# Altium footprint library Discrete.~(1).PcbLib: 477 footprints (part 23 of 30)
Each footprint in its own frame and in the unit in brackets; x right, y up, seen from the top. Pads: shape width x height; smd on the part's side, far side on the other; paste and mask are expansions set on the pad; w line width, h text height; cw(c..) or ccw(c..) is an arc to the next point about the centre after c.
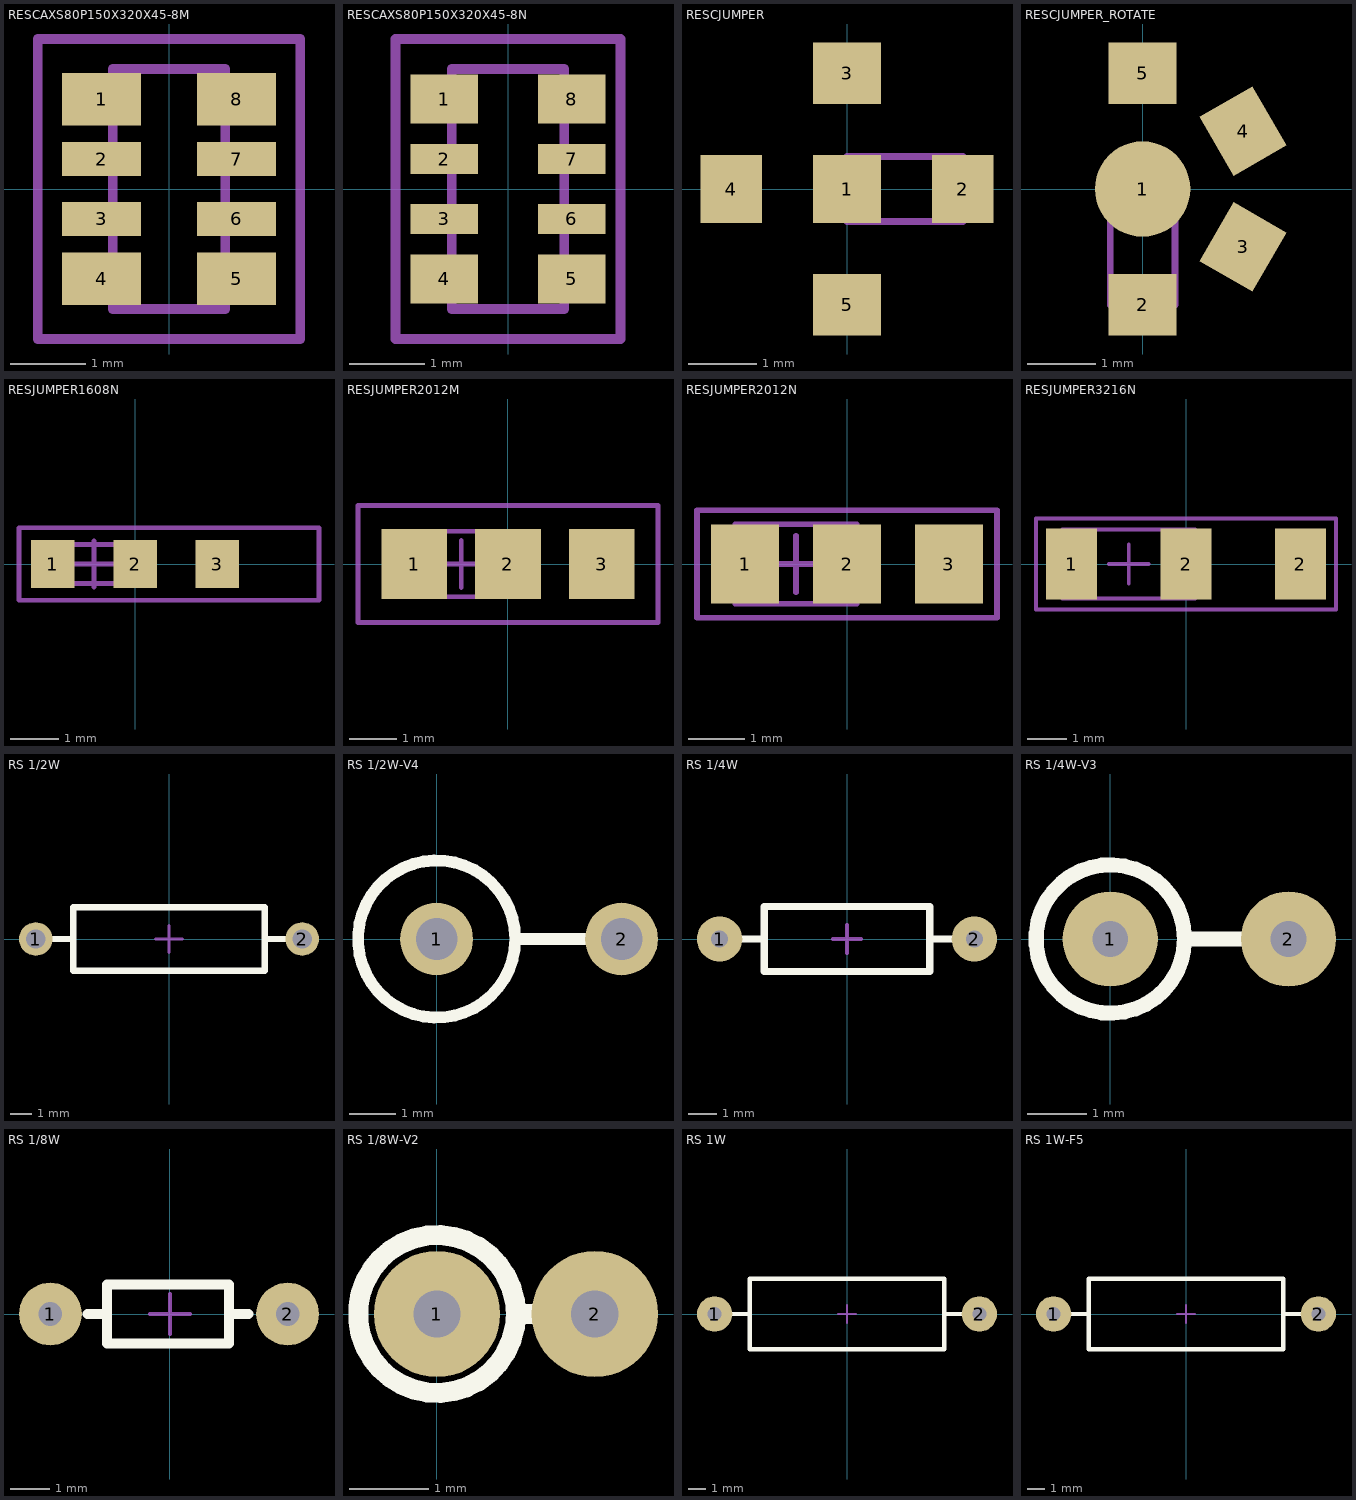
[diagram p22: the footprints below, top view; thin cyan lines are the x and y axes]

## RESCAXS80P150X320X45-8M [mm] "Resistor Array 0603X4 S-VERSION"
pads (8):
  rect 1.05x0.7 smd mask+0: 1(-0.9,1.2) 4(-0.9,-1.2) 5(0.9,-1.2) 8(0.9,1.2)
  rect 1.05x0.45 smd mask+0: 2(-0.9,0.4) 3(-0.9,-0.4) 6(0.9,-0.4) 7(0.9,0.4)
Mechanical 13:
  lines w0.127: -0.75,-1.6 -0.75,1.6 0.75,1.6 0.75,-1.6 -0.75,-1.6
Mechanical 15:
  lines w0.127: -1.75,-2 1.75,-2 1.75,2 -1.75,2 -1.75,-2
3D body "User Library-TC164.STEP": height 0.55, standoff 0, extent -0.8,-1.6 0.8,1.6

## RESCAXS80P150X320X45-8N [mm] "Resistor Array 0603X4 S-VERSION"
pads (8):
  rect 0.9x0.65 smd mask+0: 1(-0.85,1.2) 4(-0.85,-1.2) 5(0.85,-1.2) 8(0.85,1.2)
  rect 0.9x0.4 smd mask+0: 2(-0.85,0.4) 3(-0.85,-0.4) 6(0.85,-0.4) 7(0.85,0.4)
Mechanical 13:
  lines w0.127: -0.75,-1.6 0.75,-1.6 0.75,1.6 -0.75,1.6 -0.75,-1.6
Mechanical 15:
  lines w0.127: -1.5,-2 -1.5,2 1.5,2 1.5,-2 -1.5,-2
3D body "User Library-TC164.STEP": height 0.55, standoff 0, extent -0.8,-1.6 0.8,1.6

## RESCJUMPER [mm]
pads (5):
  rect 1x1 smd: 1(0,0)
  rect 0.9x1 smd: 2(1.7,0) 4(-1.7,0)
  rect 1x0.9 smd: 3(0,1.7) 5(0,-1.7)
Mechanical 13:
  lines w0.1: 0,-0.475 0,0.475 1.7,0.475 1.7,-0.475 0,-0.475
3D body: height 0.6, standoff 0, extent 0,-0.475 1.7,0.475

## RESCJUMPER_ROTATE [mm]
pads (5):
  round 1.4 smd: 1(0,0)
  rect 1x0.9 smd: 2(0,-1.7) 5(0,1.7)
  rect 1x0.9 smd rot 60: 3(1.472,-0.85)
  rect 1x0.9 smd rot 120: 4(1.472,0.85)
Mechanical 13:
  lines w0.1: -0.475,-1.7 -0.475,0 0.475,0 0.475,-1.7 -0.475,-1.7
3D body: height 0.6, standoff 0, extent -0.475,-1.7 0.475,0

## RESJUMPER1608N [mm] "Chip Resistor, Body 1.6x0.8mm, IPC Medium Density"
height 0.6
pads (3):
  rect 0.9x1 smd: 1(-1.7,0) 2(0,0) 3(1.7,0)
Mechanical 13:
  lines w0.1: -1.65,-0.4 -0.051,-0.4 -0.051,0.4 -1.65,0.4 -1.65,-0.4
Mechanical 15:
  lines w0.1: -1.325,0 -0.375,0 ; -0.85,-0.475 -0.85,0.475 ; -2.4,-0.75 3.8,-0.75 3.8,0.75 -2.4,0.75 -2.4,-0.75
3D body "R 0603.STEP": height 0.4, standoff 0, extent -1.65,-0.4 -0.05,0.4

## RESJUMPER2012M [mm]
pads (3):
  rect 1.4x1.5 smd: 1(-2,0) 2(0,0) 3(2,0)
Mechanical 13:
  lines w0.1: -2.075,-0.7 0.075,-0.7 0.075,0.7 -2.075,0.7 -2.075,-0.7
Mechanical 15:
  lines w0.1: -1.5,0 -0.5,0 ; -1,-0.5 -1,0.5 ; -3.2,-1.25 3.2,-1.25 3.2,1.25 -3.2,1.25 -3.2,-1.25
3D body: height 0.65, standoff 0, extent -2.075,-0.7 0.075,0.7

## RESJUMPER2012N [mm]
pads (3):
  rect 1.2x1.4 smd: 1(-1.8,0) 2(0,0) 3(1.8,0)
Mechanical 13:
  lines w0.1: -1.975,-0.7 -1.975,0.7 0.175,0.7 0.175,-0.7 -1.975,-0.7
Mechanical 15:
  lines w0.1: -1.4,0 -0.4,0 ; -0.9,-0.5 -0.9,0.5 ; -2.65,-0.95 -2.65,0.95 2.65,0.95 2.65,-0.95 -2.65,-0.95
3D body: height 0.65, standoff 0, extent -1.975,-0.7 0.175,0.7

## RESJUMPER3216N [mm] "Chip Resistor, Body 3.2x1.6mm, IPC Medium Density"
height 0.71
pads (3):
  rect 1.3x1.8 smd: 1(-2.9,0) 2(0,0) 2(2.9,0)
Mechanical 13:
  lines w0.1: -3.125,-0.875 0.225,-0.875 0.225,0.875 -3.125,0.875 -3.125,-0.875
Mechanical 15:
  lines w0.1: -1.95,0 -0.95,0 ; -1.45,-0.5 -1.45,0.5 ; -3.8,-1.15 3.8,-1.15 3.8,1.15 -3.8,1.15 -3.8,-1.15
3D body: height 0.71, standoff 0, extent -3.125,-0.875 0.225,0.875

## RS 1/2W [mm] "直插色环电阻，脚距12.5mm，直径3mm"
pads (2):
  round 1.575 hole 0.9: 1(-6.25,0) 2(6.25,0)
Top Overlay:
  lines w0.305: -5.5,0 -4.5,0 ; 4.5,0 5.5,0 ; -4.5,-1.5 -4.5,1.5 4.5,1.5 4.5,-1.5 -4.5,-1.5
Mechanical 15:
  lines w0.127: -0.635,0 0.635,0 ; 0,-0.635 0,0.635
3D body "RS 1-2W.STEP": height 3.11, standoff -3.4, extent -6.5,-1.51 6.5,1.51

## RS 1/2W-V4 [mil] "直插色环电阻，脚距4mm，直径3mm"
pads (2):
  round 62 hole 35.43: 1(0,0) 2(157.48,0)
Top Overlay:
  circle w10: c0,0 r66.93
  lines w10: 66.93,0 133.86,0
3D body "RS 1-2W-V4.STEP": height 423.17, standoff -137.89, extent -59.44,-59.44 167.33,59.46

## RS 1/4W [mm] "直插色环电阻，脚距9mm，直径2.3mm"
pads (2):
  round 1.6 hole 0.6: 1(-4.5,0) 2(4.5,0)
Top Overlay:
  lines w0.254: -3.683,0 -3.048,0 ; 3.048,0 3.683,0 ; -2.921,-1.143 2.921,-1.143 2.921,1.143 -2.921,1.143 -2.921,-1.143
Mechanical 15:
  lines w0.127: -0.508,0 0.508,0 ; 0,-0.508 0,0.508
3D body "RS 1-4W.STEP": height 2.32, standoff -3.49, extent -4.725,-1.16 4.725,1.16

## RS 1/4W-V3 [mm] "直插色环电阻，脚距3mm，直径2.3mm"
pads (2):
  round 1.6 hole 0.6: 1(0,0) 2(3,0)
Top Overlay:
  circle w0.254: c0,0 r1.25
  lines w0.254: 1.25,0 2.5,0
3D body "RS 1-4W-V3.STEP": height 7.42, standoff -3.5, extent -1.16,-1.16 3.225,1.16

## RS 1/8W [mm] "直插色环电阻，脚距6mm，直径1.5mm"
pads (2):
  round 1.6 hole 0.6: 1(-3.048,0) 2(3,0)
Top Overlay:
  lines w0.254: -2.1,0 -1.6,0 ; 2,0 1.5,0 ; -1.6,0 -1.6,-0.75 1.5,-0.75 1.5,0 ; -1.6,0 -1.6,0.75 1.5,0.75 1.5,0
Mechanical 15:
  lines w0.1: -0.508,0 0.508,0 ; 0,-0.508 0,0.508
3D body "RS 1-8W.STEP": height 1.52, standoff -3.49, extent -3.225,-0.757 3.225,0.757

## RS 1/8W-V2 [mm] "直插色环电阻，脚距2mm，直径1.5mm"
pads (2):
  round 1.6 hole 0.6: 1(0,0) 2(2,0)
Top Overlay:
  circle w0.254: c0,0 r1
  lines w0.254: 1,0 2,0
3D body "RS 1-8W-V2.STEP": height 4.02, standoff -3.65, extent -0.757,-0.757 2.225,0.757

## RS 1W [mm] "直插色环电阻，脚距15mm，直径4mm"
pads (2):
  round 2 hole 0.8: 1(-7.5,0) 2(7.5,0)
Top Overlay:
  lines w0.254: -6.5,0 -5.5,0 ; 5.5,0 6.5,0 ; -5.5,-2 5.5,-2 5.5,2 -5.5,2 -5.5,-2
Mechanical 15:
  lines w0.1: -0.508,0 0.508,0 ; 0,-0.508 0,0.508
3D body "RS 1W.STEP": height 4.11, standoff -3.4, extent -7.8,-2.01 7.8,2.01

## RS 1W-F5 [mm] "直插色环电阻，脚距15mm，直径4mm，浮空5mm"
pads (2):
  round 2 hole 0.8: 1(-7.5,0) 2(7.5,0)
Top Overlay:
  lines w0.254: -6.5,0 -5.5,0 ; 5.5,0 6.5,0 ; -5.5,-2 -5.5,2 5.5,2 5.5,-2 -5.5,-2
Mechanical 15:
  lines w0.1: -0.508,0 0.508,0 ; 0,-0.508 0,0.508
3D body "RS 1W-F5.STEP": height 9.01, standoff -3.5, extent -7.8,-2.01 7.8,2.01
